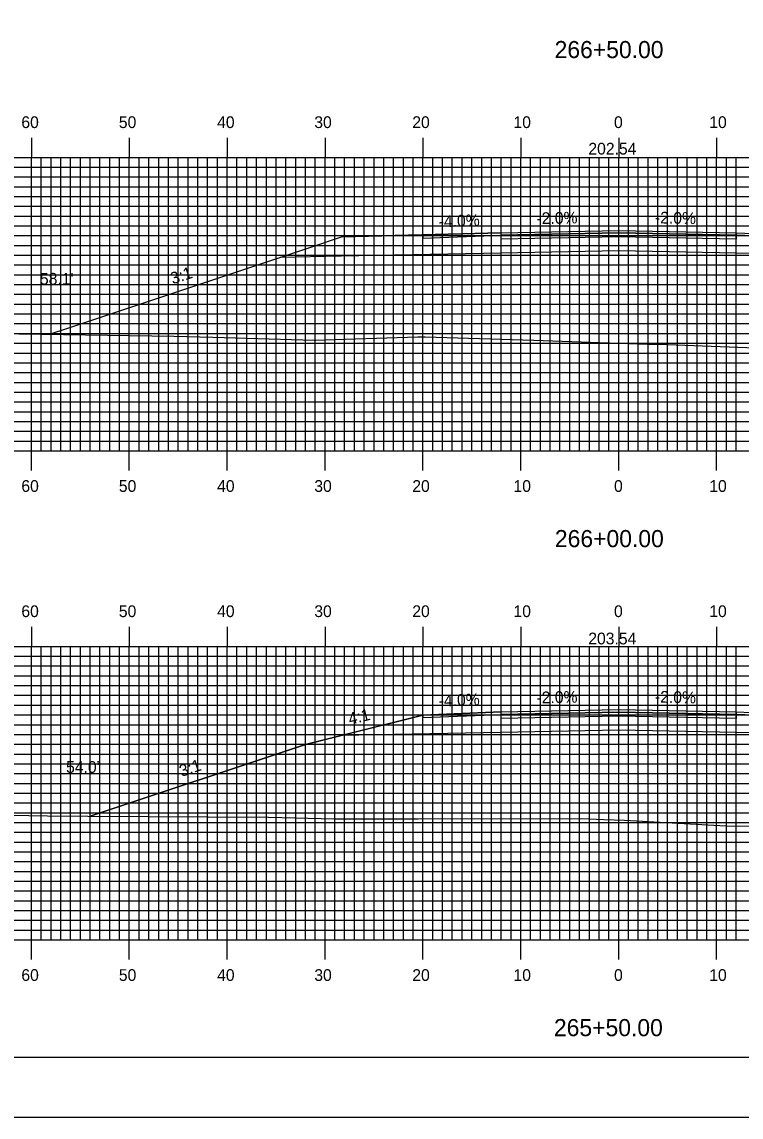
# Model space of a CAD drawing. Extents: x 1807438 to 1807782, y 442591 to 442811.
# Drawn here: x 1807543.3 to 1807616.8, y 442590.5 to 442702.5 of the extents above; entities that cross this region are included whole.
import ezdxf

# ---------------------------------------------------------------- set-up
doc = ezdxf.new("R2010")
doc.units = 0
for name, color, linetype in [('ANNOTATION', 7, 'Continuous'), ('BORDER', 7, 'Continuous'), ('D_Roadway_Centerline', 7, 'Continuous'), ('D_Roadway_Centerline_Text', 7, 'Continuous'), ('D_Roadway_Drive_Gravel', 7, 'Continuous'), ('D_Roadway_Edge_Shoulder', 7, 'Continuous'), ('D_Roadway_Edge_TW', 7, 'Continuous'), ('D_Roadway_Pavement', 7, 'Continuous'), ('D_Roadway_SlopeLines', 7, 'Continuous'), ('D_Roadway_SubGrade', 7, 'Continuous'), ('D_Text_Standard', 7, 'Continuous'), ('H_V ANNOTATION', 7, 'Continuous'), ('MAJOR', 7, 'Continuous'), ('MINOR', 7, 'Continuous'), ('PLOT BOUNDARY', 7, 'Continuous'), ('S_Roadway_Centerline', 7, 'Continuous')]:
    doc.layers.add(name, color=color, linetype=linetype)

msp = doc.modelspace()

# ---------------------------------------------------------------- linework, layer by layer
at = {"layer": 'BORDER'}
msp.add_lwpolyline([(1807454.67, 442596.67), (1807774.67, 442596.67), (1807774.67, 442806.67), (1807454.67, 442806.67)], close=True, dxfattribs=at)
at = {"layer": 'D_Roadway_Centerline'}
msp.add_lwpolyline([(1807550.27, 442621.31), (1807572.27, 442628.65), (1807575.91, 442629.56), (1807584.27, 442631.65), (1807592.27, 442631.97), (1807604.27, 442632.21), (1807616.27, 442631.97), (1807624.27, 442631.65), (1807632.63, 442629.56), (1807636.27, 442628.65), (1807663.94, 442619.42)], dxfattribs=at)
at = {"layer": 'D_Roadway_Drive_Gravel'}
msp.add_lwpolyline([(1807592.27, 442680.97), (1807584.15, 442680.76), (1807576.03, 442680.55), (1807572.79, 442679.47)], dxfattribs=at)
at = {"layer": 'D_Roadway_Edge_Shoulder'}
for points in [[(1807616.27, 442680.97), (1807624.27, 442680.65), (1807624.27, 442680.4), (1807616.27, 442680.72)], [(1807592.27, 442631.97), (1807584.27, 442631.65), (1807584.27, 442631.4), (1807592.27, 442631.72)], [(1807616.27, 442631.97), (1807624.27, 442631.65), (1807624.27, 442631.4), (1807616.27, 442631.72)]]:
    msp.add_lwpolyline(points, close=True, dxfattribs=at)
at = {"layer": 'D_Roadway_Edge_TW'}
for points in [[(1807592.27, 442680.72), (1807592.27, 442680.97), (1807604.27, 442681.21), (1807616.27, 442680.97), (1807616.27, 442680.72), (1807604.27, 442680.96)], [(1807592.27, 442631.72), (1807592.27, 442631.97), (1807604.27, 442632.21), (1807616.27, 442631.97), (1807616.27, 442631.72), (1807604.27, 442631.96)]]:
    msp.add_lwpolyline(points, close=True, dxfattribs=at)
at = {"layer": 'D_Roadway_Pavement'}
for points in [[(1807592.27, 442680.3), (1807592.27, 442680.72), (1807604.27, 442680.96), (1807616.27, 442680.72), (1807616.27, 442680.3), (1807604.27, 442680.54)], [(1807592.27, 442631.3), (1807592.27, 442631.72), (1807604.27, 442631.96), (1807616.27, 442631.72), (1807616.27, 442631.3), (1807604.27, 442631.54)]]:
    msp.add_lwpolyline(points, close=True, dxfattribs=at)
at = {"layer": 'D_Roadway_SlopeLines'}
for points in [[(1807576.03, 442680.55), (1807572.79, 442679.47), (1807547.95, 442671.17)], [(1807584.27, 442631.65), (1807572.27, 442628.65), (1807550.27, 442621.31)]]:
    msp.add_lwpolyline(points, dxfattribs=at)
at = {"layer": 'D_Roadway_SubGrade'}
for p, q in [((1807576.03, 442680.55), (1807592.27, 442680.97)), ((1807584.27, 442680.65), (1807584.27, 442680.76)), ((1807575.91, 442678.56), (1807569.68, 442678.43)), ((1807547.95, 442671.17), (1807546.2, 442670.59))]:
    msp.add_line(p, q, dxfattribs=at)
msp.add_lwpolyline([(1807584.27, 442680.65), (1807584.27, 442680.4), (1807592.27, 442680.72), (1807604.27, 442680.96), (1807616.27, 442680.72), (1807624.27, 442680.4), (1807624.27, 442680.65), (1807632.63, 442678.56), (1807616.27, 442678.88), (1807604.27, 442679.12), (1807592.27, 442678.88), (1807575.91, 442678.56)], dxfattribs=at)
msp.add_lwpolyline([(1807592.27, 442629.88), (1807575.91, 442629.56), (1807584.27, 442631.65), (1807584.27, 442631.4), (1807592.27, 442631.72), (1807604.27, 442631.96), (1807616.27, 442631.72), (1807624.27, 442631.4), (1807624.27, 442631.65), (1807632.63, 442629.56), (1807616.27, 442629.88), (1807604.27, 442630.12)], close=True, dxfattribs=at)
at = {"layer": 'MAJOR'}
for p, q in [((1807544.27, 442690.67), (1807544.27, 442688.67)), ((1807554.27, 442690.67), (1807554.27, 442688.67)), ((1807564.27, 442690.67), (1807564.27, 442688.67)), ((1807574.27, 442690.67), (1807574.27, 442688.67)), ((1807584.27, 442690.67), (1807584.27, 442688.67)), ((1807594.27, 442690.67), (1807594.27, 442688.67)), ((1807604.27, 442690.67), (1807604.27, 442688.67)), ((1807614.27, 442690.67), (1807614.27, 442688.67)), ((1807464.27, 442688.67), (1807744.27, 442688.67)), ((1807464.27, 442688.67), (1807744.27, 442688.67)), ((1807544.27, 442658.67), (1807544.27, 442688.67)), ((1807554.27, 442658.67), (1807554.27, 442688.67)), ((1807564.27, 442658.67), (1807564.27, 442688.67)), ((1807574.27, 442658.67), (1807574.27, 442688.67)), ((1807584.27, 442658.67), (1807584.27, 442688.67)), ((1807594.27, 442658.67), (1807594.27, 442688.67)), ((1807604.27, 442658.67), (1807604.27, 442688.67)), ((1807614.27, 442658.67), (1807614.27, 442688.67)), ((1807464.27, 442683.67), (1807744.27, 442683.67)), ((1807464.27, 442678.67), (1807744.27, 442678.67)), ((1807464.27, 442673.67), (1807744.27, 442673.67)), ((1807464.27, 442668.67), (1807744.27, 442668.67)), ((1807464.27, 442663.67), (1807744.27, 442663.67)), ((1807464.27, 442658.67), (1807744.27, 442658.67)), ((1807464.27, 442658.67), (1807744.27, 442658.67)), ((1807544.27, 442656.66), (1807544.27, 442658.67)), ((1807554.27, 442656.66), (1807554.27, 442658.67)), ((1807564.27, 442656.66), (1807564.27, 442658.67)), ((1807574.27, 442656.66), (1807574.27, 442658.67)), ((1807584.27, 442656.66), (1807584.27, 442658.67)), ((1807594.27, 442656.66), (1807594.27, 442658.67)), ((1807604.27, 442656.66), (1807604.27, 442658.67)), ((1807614.27, 442656.66), (1807614.27, 442658.67)), ((1807544.27, 442640.67), (1807544.27, 442638.67)), ((1807554.27, 442640.67), (1807554.27, 442638.67)), ((1807564.27, 442640.67), (1807564.27, 442638.67)), ((1807574.27, 442640.67), (1807574.27, 442638.67)), ((1807584.27, 442640.67), (1807584.27, 442638.67)), ((1807594.27, 442640.67), (1807594.27, 442638.67)), ((1807604.27, 442640.67), (1807604.27, 442638.67)), ((1807614.27, 442640.67), (1807614.27, 442638.67)), ((1807464.27, 442638.67), (1807744.27, 442638.67)), ((1807464.27, 442638.67), (1807744.27, 442638.67)), ((1807544.27, 442608.67), (1807544.27, 442638.67)), ((1807554.27, 442608.67), (1807554.27, 442638.67)), ((1807564.27, 442608.67), (1807564.27, 442638.67)), ((1807574.27, 442608.67), (1807574.27, 442638.67)), ((1807584.27, 442608.67), (1807584.27, 442638.67)), ((1807594.27, 442608.67), (1807594.27, 442638.67)), ((1807604.27, 442608.67), (1807604.27, 442638.67)), ((1807614.27, 442608.67), (1807614.27, 442638.67)), ((1807464.27, 442633.67), (1807744.27, 442633.67)), ((1807464.27, 442628.67), (1807744.27, 442628.67)), ((1807464.27, 442623.67), (1807744.27, 442623.67)), ((1807464.27, 442618.67), (1807744.27, 442618.67)), ((1807464.27, 442613.67), (1807744.27, 442613.67)), ((1807464.27, 442608.67), (1807744.27, 442608.67)), ((1807464.27, 442608.67), (1807744.27, 442608.67)), ((1807544.27, 442606.66), (1807544.27, 442608.67)), ((1807554.27, 442606.66), (1807554.27, 442608.67)), ((1807564.27, 442606.66), (1807564.27, 442608.67)), ((1807574.27, 442606.66), (1807574.27, 442608.67)), ((1807584.27, 442606.66), (1807584.27, 442608.67)), ((1807594.27, 442606.66), (1807594.27, 442608.67)), ((1807604.27, 442606.66), (1807604.27, 442608.67)), ((1807614.27, 442606.66), (1807614.27, 442608.67))]:
    msp.add_line(p, q, dxfattribs=at)
at = {"layer": 'MINOR'}
for p, q in [((1807545.27, 442658.67), (1807545.27, 442688.67)), ((1807546.27, 442658.67), (1807546.27, 442688.67)), ((1807547.27, 442658.67), (1807547.27, 442688.67)), ((1807548.27, 442658.67), (1807548.27, 442688.67)), ((1807549.27, 442658.67), (1807549.27, 442688.67)), ((1807550.27, 442658.67), (1807550.27, 442688.67)), ((1807551.27, 442658.67), (1807551.27, 442688.67)), ((1807552.27, 442658.67), (1807552.27, 442688.67)), ((1807553.27, 442658.67), (1807553.27, 442688.67)), ((1807555.27, 442658.67), (1807555.27, 442688.67)), ((1807556.27, 442658.67), (1807556.27, 442688.67)), ((1807557.27, 442658.67), (1807557.27, 442688.67)), ((1807558.27, 442658.67), (1807558.27, 442688.67)), ((1807559.27, 442658.67), (1807559.27, 442688.67)), ((1807560.27, 442658.67), (1807560.27, 442688.67)), ((1807561.27, 442658.67), (1807561.27, 442688.67)), ((1807562.27, 442658.67), (1807562.27, 442688.67)), ((1807563.27, 442658.67), (1807563.27, 442688.67)), ((1807565.27, 442658.67), (1807565.27, 442688.67)), ((1807566.27, 442658.67), (1807566.27, 442688.67)), ((1807567.27, 442658.67), (1807567.27, 442688.67)), ((1807568.27, 442658.67), (1807568.27, 442688.67)), ((1807569.27, 442658.67), (1807569.27, 442688.67)), ((1807570.27, 442658.67), (1807570.27, 442688.67)), ((1807571.27, 442658.67), (1807571.27, 442688.67)), ((1807572.27, 442658.67), (1807572.27, 442688.67)), ((1807573.27, 442658.67), (1807573.27, 442688.67)), ((1807575.27, 442658.67), (1807575.27, 442688.67)), ((1807576.27, 442658.67), (1807576.27, 442688.67)), ((1807577.27, 442658.67), (1807577.27, 442688.67)), ((1807578.27, 442658.67), (1807578.27, 442688.67)), ((1807579.27, 442658.67), (1807579.27, 442688.67)), ((1807580.27, 442658.67), (1807580.27, 442688.67)), ((1807581.27, 442658.67), (1807581.27, 442688.67)), ((1807582.27, 442658.67), (1807582.27, 442688.67)), ((1807583.27, 442658.67), (1807583.27, 442688.67)), ((1807585.27, 442658.67), (1807585.27, 442688.67)), ((1807586.27, 442658.67), (1807586.27, 442688.67)), ((1807587.27, 442658.67), (1807587.27, 442688.67)), ((1807588.27, 442658.67), (1807588.27, 442688.67)), ((1807589.27, 442658.67), (1807589.27, 442688.67)), ((1807590.27, 442658.67), (1807590.27, 442688.67)), ((1807591.27, 442658.67), (1807591.27, 442688.67)), ((1807592.27, 442658.67), (1807592.27, 442688.67)), ((1807593.27, 442658.67), (1807593.27, 442688.67)), ((1807595.27, 442658.67), (1807595.27, 442688.67)), ((1807596.27, 442658.67), (1807596.27, 442688.67)), ((1807597.27, 442658.67), (1807597.27, 442688.67)), ((1807598.27, 442658.67), (1807598.27, 442688.67)), ((1807599.27, 442658.67), (1807599.27, 442688.67)), ((1807600.27, 442658.67), (1807600.27, 442688.67)), ((1807601.27, 442658.67), (1807601.27, 442688.67)), ((1807602.27, 442658.67), (1807602.27, 442688.67)), ((1807603.27, 442658.67), (1807603.27, 442688.67)), ((1807605.27, 442658.67), (1807605.27, 442688.67)), ((1807606.27, 442658.67), (1807606.27, 442688.67)), ((1807607.27, 442658.67), (1807607.27, 442688.67)), ((1807608.27, 442658.67), (1807608.27, 442688.67)), ((1807609.27, 442658.67), (1807609.27, 442688.67)), ((1807610.27, 442658.67), (1807610.27, 442688.67)), ((1807611.27, 442658.67), (1807611.27, 442688.67)), ((1807612.27, 442658.67), (1807612.27, 442688.67)), ((1807613.27, 442658.67), (1807613.27, 442688.67)), ((1807615.27, 442658.67), (1807615.27, 442688.67)), ((1807616.27, 442658.67), (1807616.27, 442688.67)), ((1807464.27, 442687.67), (1807744.27, 442687.67)), ((1807464.27, 442686.67), (1807744.27, 442686.67)), ((1807464.27, 442685.67), (1807744.27, 442685.67)), ((1807464.27, 442684.67), (1807744.27, 442684.67)), ((1807464.27, 442682.67), (1807744.27, 442682.67)), ((1807464.27, 442681.67), (1807744.27, 442681.67)), ((1807464.27, 442680.67), (1807744.27, 442680.67)), ((1807464.27, 442679.67), (1807744.27, 442679.67)), ((1807464.27, 442677.67), (1807744.27, 442677.67)), ((1807464.27, 442676.67), (1807744.27, 442676.67)), ((1807464.27, 442675.67), (1807744.27, 442675.67)), ((1807464.27, 442674.67), (1807744.27, 442674.67)), ((1807464.27, 442672.67), (1807744.27, 442672.67)), ((1807464.27, 442671.67), (1807744.27, 442671.67)), ((1807464.27, 442670.67), (1807744.27, 442670.67)), ((1807464.27, 442669.67), (1807744.27, 442669.67)), ((1807464.27, 442667.67), (1807744.27, 442667.67)), ((1807464.27, 442666.67), (1807744.27, 442666.67)), ((1807464.27, 442665.67), (1807744.27, 442665.67)), ((1807464.27, 442664.67), (1807744.27, 442664.67)), ((1807464.27, 442662.67), (1807744.27, 442662.67)), ((1807464.27, 442661.67), (1807744.27, 442661.67)), ((1807464.27, 442660.67), (1807744.27, 442660.67)), ((1807464.27, 442659.67), (1807744.27, 442659.67)), ((1807545.27, 442608.67), (1807545.27, 442638.67)), ((1807546.27, 442608.67), (1807546.27, 442638.67)), ((1807547.27, 442608.67), (1807547.27, 442638.67)), ((1807548.27, 442608.67), (1807548.27, 442638.67)), ((1807549.27, 442608.67), (1807549.27, 442638.67)), ((1807550.27, 442608.67), (1807550.27, 442638.67)), ((1807551.27, 442608.67), (1807551.27, 442638.67)), ((1807552.27, 442608.67), (1807552.27, 442638.67)), ((1807553.27, 442608.67), (1807553.27, 442638.67)), ((1807555.27, 442608.67), (1807555.27, 442638.67)), ((1807556.27, 442608.67), (1807556.27, 442638.67)), ((1807557.27, 442608.67), (1807557.27, 442638.67)), ((1807558.27, 442608.67), (1807558.27, 442638.67)), ((1807559.27, 442608.67), (1807559.27, 442638.67)), ((1807560.27, 442608.67), (1807560.27, 442638.67)), ((1807561.27, 442608.67), (1807561.27, 442638.67)), ((1807562.27, 442608.67), (1807562.27, 442638.67)), ((1807563.27, 442608.67), (1807563.27, 442638.67)), ((1807565.27, 442608.67), (1807565.27, 442638.67)), ((1807566.27, 442608.67), (1807566.27, 442638.67)), ((1807567.27, 442608.67), (1807567.27, 442638.67)), ((1807568.27, 442608.67), (1807568.27, 442638.67)), ((1807569.27, 442608.67), (1807569.27, 442638.67)), ((1807570.27, 442608.67), (1807570.27, 442638.67)), ((1807571.27, 442608.67), (1807571.27, 442638.67)), ((1807572.27, 442608.67), (1807572.27, 442638.67)), ((1807573.27, 442608.67), (1807573.27, 442638.67)), ((1807575.27, 442608.67), (1807575.27, 442638.67)), ((1807576.27, 442608.67), (1807576.27, 442638.67)), ((1807577.27, 442608.67), (1807577.27, 442638.67)), ((1807578.27, 442608.67), (1807578.27, 442638.67)), ((1807579.27, 442608.67), (1807579.27, 442638.67)), ((1807580.27, 442608.67), (1807580.27, 442638.67)), ((1807581.27, 442608.67), (1807581.27, 442638.67)), ((1807582.27, 442608.67), (1807582.27, 442638.67)), ((1807583.27, 442608.67), (1807583.27, 442638.67)), ((1807585.27, 442608.67), (1807585.27, 442638.67)), ((1807586.27, 442608.67), (1807586.27, 442638.67)), ((1807587.27, 442608.67), (1807587.27, 442638.67)), ((1807588.27, 442608.67), (1807588.27, 442638.67)), ((1807589.27, 442608.67), (1807589.27, 442638.67)), ((1807590.27, 442608.67), (1807590.27, 442638.67)), ((1807591.27, 442608.67), (1807591.27, 442638.67)), ((1807592.27, 442608.67), (1807592.27, 442638.67)), ((1807593.27, 442608.67), (1807593.27, 442638.67)), ((1807595.27, 442608.67), (1807595.27, 442638.67)), ((1807596.27, 442608.67), (1807596.27, 442638.67)), ((1807597.27, 442608.67), (1807597.27, 442638.67)), ((1807598.27, 442608.67), (1807598.27, 442638.67)), ((1807599.27, 442608.67), (1807599.27, 442638.67)), ((1807600.27, 442608.67), (1807600.27, 442638.67)), ((1807601.27, 442608.67), (1807601.27, 442638.67)), ((1807602.27, 442608.67), (1807602.27, 442638.67)), ((1807603.27, 442608.67), (1807603.27, 442638.67)), ((1807605.27, 442608.67), (1807605.27, 442638.67)), ((1807606.27, 442608.67), (1807606.27, 442638.67)), ((1807607.27, 442608.67), (1807607.27, 442638.67)), ((1807608.27, 442608.67), (1807608.27, 442638.67)), ((1807609.27, 442608.67), (1807609.27, 442638.67)), ((1807610.27, 442608.67), (1807610.27, 442638.67)), ((1807611.27, 442608.67), (1807611.27, 442638.67)), ((1807612.27, 442608.67), (1807612.27, 442638.67)), ((1807613.27, 442608.67), (1807613.27, 442638.67)), ((1807615.27, 442608.67), (1807615.27, 442638.67)), ((1807616.27, 442608.67), (1807616.27, 442638.67)), ((1807464.27, 442637.67), (1807744.27, 442637.67)), ((1807464.27, 442636.67), (1807744.27, 442636.67)), ((1807464.27, 442635.67), (1807744.27, 442635.67)), ((1807464.27, 442634.67), (1807744.27, 442634.67)), ((1807464.27, 442632.67), (1807744.27, 442632.67)), ((1807464.27, 442631.67), (1807744.27, 442631.67)), ((1807464.27, 442630.67), (1807744.27, 442630.67)), ((1807464.27, 442629.67), (1807744.27, 442629.67)), ((1807464.27, 442627.67), (1807744.27, 442627.67)), ((1807464.27, 442626.67), (1807744.27, 442626.67)), ((1807464.27, 442625.67), (1807744.27, 442625.67)), ((1807464.27, 442624.67), (1807744.27, 442624.67)), ((1807464.27, 442622.67), (1807744.27, 442622.67)), ((1807464.27, 442621.67), (1807744.27, 442621.67)), ((1807464.27, 442620.67), (1807744.27, 442620.67)), ((1807464.27, 442619.67), (1807744.27, 442619.67)), ((1807464.27, 442617.67), (1807744.27, 442617.67)), ((1807464.27, 442616.67), (1807744.27, 442616.67)), ((1807464.27, 442615.67), (1807744.27, 442615.67)), ((1807464.27, 442614.67), (1807744.27, 442614.67)), ((1807464.27, 442612.67), (1807744.27, 442612.67)), ((1807464.27, 442611.67), (1807744.27, 442611.67)), ((1807464.27, 442610.67), (1807744.27, 442610.67)), ((1807464.27, 442609.67), (1807744.27, 442609.67))]:
    msp.add_line(p, q, dxfattribs=at)
at = {"layer": 'PLOT BOUNDARY'}
msp.add_lwpolyline([(1807438.49, 442590.55), (1807778.49, 442590.55), (1807778.49, 442810.55), (1807438.49, 442810.55)], close=True, dxfattribs=at)
at = {"layer": 'S_Roadway_Centerline'}
for points in [[(1807543.03, 442670.64), (1807558.83, 442670.39), (1807562.82, 442670.28), (1807573.14, 442669.98), (1807583.75, 442670.32), (1807584.48, 442670.34), (1807595.61, 442669.99), (1807607.18, 442669.59), (1807608.44, 442669.57), (1807610.13, 442669.5), (1807626.36, 442668.9), (1807635.04, 442668.88), (1807642.94, 442668.94), (1807648.6, 442668.86), (1807666.43, 442668.5)], [(1807542.11, 442621.43), (1807545.92, 442621.36), (1807550.02, 442621.31), (1807568.49, 442621.2), (1807575.25, 442621.04), (1807583.79, 442621.05), (1807600.51, 442621.06), (1807602.75, 442620.99), (1807604.87, 442620.9), (1807615.2, 442620.31), (1807625.66, 442620.19), (1807638.28, 442620.19), (1807647.75, 442620.23), (1807653.42, 442620.03), (1807660.85, 442619.54), (1807668.49, 442619.26)]]:
    msp.add_lwpolyline(points, dxfattribs=at)

# ---------------------------------------------------------------- texts
at = {"layer": 'ANNOTATION'}
for s, rotation, p in [('-2.0%', 1.1458, (1807595.88, 442681.84)), ('-2.0%', 358.8542, (1807607.96, 442681.93)), ('-4.0%', 2.2906, (1807585.9, 442681.51)), ('3:1', 18.4348, (1807558.71, 442675.68)), ('-4.0%', 2.2906, (1807585.9, 442632.51)), ('-2.0%', 1.1458, (1807595.88, 442632.84)), ('-2.0%', 358.8542, (1807607.96, 442632.93)), ('4:1', 14.0362, (1807576.81, 442630.64)), ('3:1', 18.4348, (1807559.61, 442625.33))]:
    msp.add_text(s, height=1.2, rotation=rotation, dxfattribs=at).set_placement(p)
at = {"layer": 'D_Roadway_Centerline'}
for s, p in [('C', (1807604.27, 442681.21)), ('L', (1807604.27, 442681.2)), ('C', (1807604.27, 442632.21)), ('L', (1807604.27, 442632.2))]:
    msp.add_text(s, height=0.0146, dxfattribs=at).set_placement(p)
at = {"layer": 'D_Roadway_Centerline_Text'}
for s, p in [('202.54', (1807601.17, 442688.96)), ('203.54', (1807601.16, 442638.88))]:
    msp.add_text(s, height=1.2, dxfattribs=at).set_placement(p)
at = {"layer": 'D_Text_Standard'}
for s, p in [("58.1'", (1807545.14, 442675.66)), ("54.0'", (1807547.81, 442625.74))]:
    msp.add_text(s, height=1.2, dxfattribs=at).set_placement(p)
at = {"layer": 'H_V ANNOTATION'}
for s, height, p in [('266+50.00', 1.75, (1807597.72, 442698.82)), ('60', 1.2, (1807543.24, 442691.67)), ('50', 1.2, (1807553.2, 442691.67)), ('40', 1.2, (1807563.24, 442691.67)), ('30', 1.2, (1807573.17, 442691.67)), ('20', 1.2, (1807583.18, 442691.67)), ('10', 1.2, (1807593.52, 442691.67)), ('0', 1.2, (1807603.79, 442691.67)), ('10', 1.2, (1807613.52, 442691.67)), ('60', 1.2, (1807543.24, 442654.47)), ('50', 1.2, (1807553.2, 442654.47)), ('40', 1.2, (1807563.24, 442654.47)), ('30', 1.2, (1807573.17, 442654.47)), ('20', 1.2, (1807583.18, 442654.47)), ('10', 1.2, (1807593.52, 442654.47)), ('0', 1.2, (1807603.79, 442654.47)), ('10', 1.2, (1807613.52, 442654.47)), ('266+00.00', 1.75, (1807597.75, 442648.82)), ('60', 1.2, (1807543.24, 442641.67)), ('50', 1.2, (1807553.2, 442641.67)), ('40', 1.2, (1807563.24, 442641.67)), ('30', 1.2, (1807573.17, 442641.67)), ('20', 1.2, (1807583.18, 442641.67)), ('10', 1.2, (1807593.52, 442641.67)), ('0', 1.2, (1807603.79, 442641.67)), ('10', 1.2, (1807613.52, 442641.67)), ('60', 1.2, (1807543.24, 442604.47)), ('50', 1.2, (1807553.2, 442604.47)), ('40', 1.2, (1807563.24, 442604.47)), ('30', 1.2, (1807573.17, 442604.47)), ('20', 1.2, (1807583.18, 442604.47)), ('10', 1.2, (1807593.52, 442604.47)), ('0', 1.2, (1807603.79, 442604.47)), ('10', 1.2, (1807613.52, 442604.47)), ('265+50.00', 1.75, (1807597.65, 442598.82))]:
    msp.add_text(s, height=height, dxfattribs=at).set_placement(p)

doc.saveas('drawing.dxf')
